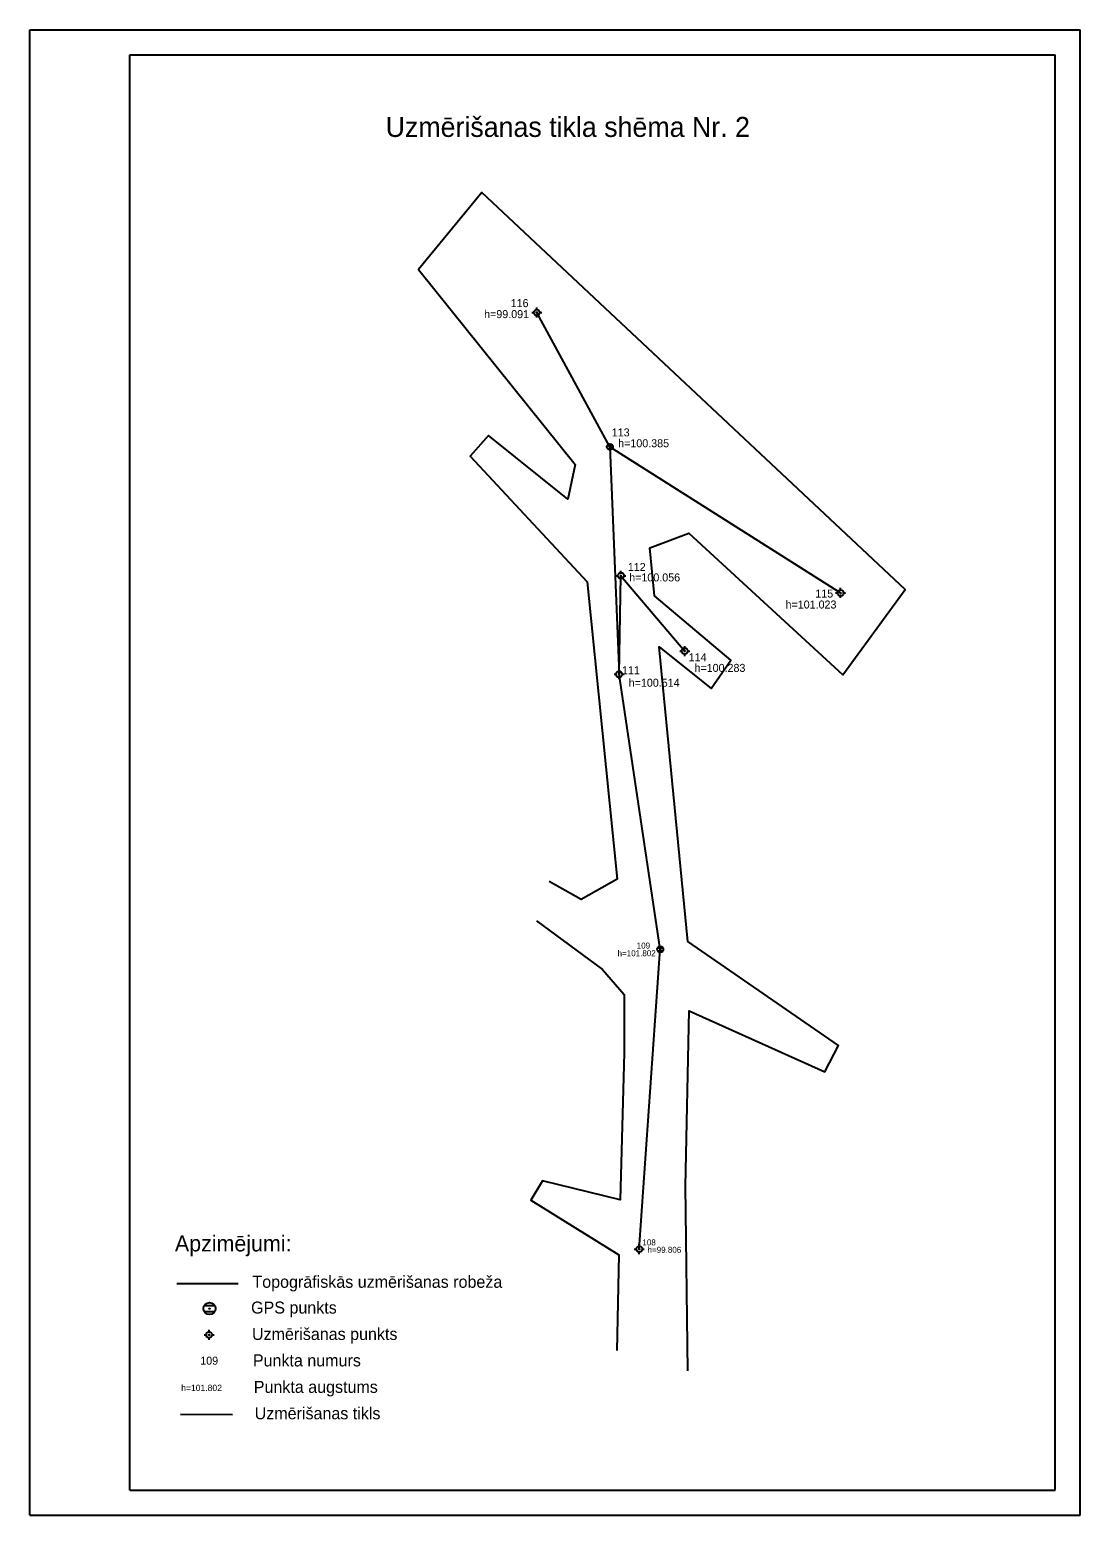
# Model space of a CAD drawing. Extents: x 615321 to 615846, y 263640 to 264383.
import ezdxf

# ---------------------------------------------------------------- set-up
doc = ezdxf.new("R2010")
doc.units = 0
for name, color, linetype in [('Level 19', 7, 'Continuous'), ('Level 25', 7, 'Continuous'), ('Level 63', 7, 'Continuous')]:
    doc.layers.add(name, color=color, linetype=linetype)

msp = doc.modelspace()

# ---------------------------------------------------------------- linework, layer by layer
at = {"layer": 'Level 19'}
for p, q in [((615572.36, 264241.43), (615573.36, 264241.43)), ((615574.86, 264242.93), (615574.86, 264243.93)), ((615611.43, 264174.34), (615574.86, 264241.43)), ((615576.36, 264241.43), (615577.36, 264241.43)), ((615574.86, 264238.93), (615574.86, 264239.93)), ((615610.13, 264175.09), (615612.73, 264175.09)), ((615611.43, 264174.34), (615615.96, 264060.66)), ((615611.43, 264174.34), (615726.66, 264101.3)), ((615610.13, 264173.59), (615612.73, 264173.59)), ((615614.44, 264109.92), (615615.44, 264109.92)), ((615615.96, 264060.66), (615616.94, 264109.92)), ((615616.94, 264111.42), (615616.94, 264112.42)), ((615616.94, 264109.92), (615648.76, 264072.27)), ((615616.94, 264107.42), (615616.94, 264108.42)), ((615618.44, 264109.92), (615619.44, 264109.92)), ((615724.16, 264101.3), (615725.16, 264101.3)), ((615726.66, 264102.8), (615726.66, 264103.8)), ((615728.16, 264101.3), (615729.16, 264101.3)), ((615726.66, 264098.8), (615726.66, 264099.8)), ((615646.26, 264072.27), (615647.26, 264072.27)), ((615648.76, 264073.77), (615648.76, 264074.77)), ((615648.76, 264069.77), (615648.76, 264070.77)), ((615650.26, 264072.27), (615651.26, 264072.27)), ((615615.96, 264062.16), (615615.96, 264063.16)), ((615613.46, 264060.66), (615614.46, 264060.66)), ((615636.56, 263923.23), (615615.96, 264060.66)), ((615615.96, 264058.16), (615615.96, 264059.16)), ((615617.46, 264060.66), (615618.46, 264060.66)), ((615626.06, 263773.35), (615636.56, 263923.23)), ((615635.26, 263923.98), (615637.86, 263923.98)), ((615635.26, 263922.48), (615637.86, 263922.48)), ((615623.56, 263773.35), (615624.56, 263773.35)), ((615626.06, 263774.86), (615626.06, 263775.86)), ((615627.56, 263773.35), (615628.56, 263773.35)), ((615626.06, 263770.86), (615626.06, 263771.86)), ((615408.69, 263745.1), (615413.88, 263745.1)), ((615408.69, 263742.1), (615413.88, 263742.1)), ((615408.61, 263730.53), (615409.61, 263730.53)), ((615411.11, 263732.03), (615411.11, 263733.03)), ((615411.11, 263728.03), (615411.11, 263729.03)), ((615412.61, 263730.53), (615413.61, 263730.53)), ((615422.8, 263690.57), (615396.83, 263690.62))]:
    msp.add_line(p, q, dxfattribs=at)
for centre, radius in [((615574.86, 264241.43), 1.5), ((615574.86, 264241.43), 0.2), ((615611.43, 264174.34), 1.5), ((615611.43, 264174.34), 0.08), ((615616.94, 264109.92), 1.5), ((615616.94, 264109.92), 0.2), ((615726.66, 264101.3), 1.5), ((615726.66, 264101.3), 0.2), ((615648.76, 264072.27), 1.5), ((615648.76, 264072.27), 0.2), ((615615.96, 264060.66), 1.5), ((615615.96, 264060.66), 0.2), ((615636.56, 263923.23), 1.5), ((615636.56, 263923.23), 0.08), ((615626.06, 263773.35), 1.5), ((615626.06, 263773.35), 0.2), ((615411.29, 263743.6), 3), ((615411.29, 263743.6), 0.16), ((615411.11, 263730.53), 1.5), ((615411.11, 263730.53), 0.2)]:
    msp.add_circle(centre, radius, dxfattribs=at)
at = {"layer": 'Level 25'}
msp.add_line((615395.01, 263756.16), (615425.57, 263756.16), dxfattribs=at)
for points in [[(615650.31, 263712.52), (615649.19, 263804.75), (615651.03, 263892.42), (615718.86, 263862), (615725.65, 263875.12), (615650.27, 263927.03), (615636.07, 264074.3), (615661.97, 264053.63), (615671.9, 264067.65), (615633.61, 264099.8), (615631.29, 264123.92), (615650.85, 264131.21), (615727.85, 264060.46), (615758.93, 264103), (615547.44, 264301.47), (615515.7, 264263), (615594.09, 264165.59), (615590.41, 264148.27), (615550.77, 264179.99), (615541.58, 264169.6), (615600.08, 264106.91), (615615.01, 263958.32), (615597.04, 263948.14), (615581.01, 263957.13)], [(615574.69, 263937.47), (615607.77, 263913.06), (615618.57, 263900.65), (615618.57, 263871.49), (615616.58, 263797.94), (615577.64, 263807.5), (615571.84, 263797.84), (615615.86, 263770.49), (615614.87, 263722.66)]]:
    msp.add_lwpolyline(points, dxfattribs=at)
at = {"layer": 'Level 63'}
for p, q in [((615321.46, 263640.32), (615321.46, 264382.82)), ((615321.46, 264382.82), (615846.46, 264382.82)), ((615846.46, 263640.32), (615846.46, 264382.82)), ((615371.46, 263652.82), (615371.46, 264370.32)), ((615371.46, 264370.32), (615833.96, 264370.32)), ((615833.96, 263652.82), (615833.96, 264370.32)), ((615371.46, 263652.82), (615833.96, 263652.82)), ((615321.46, 263640.32), (615846.46, 263640.32))]:
    msp.add_line(p, q, dxfattribs=at)

# ---------------------------------------------------------------- texts
at = {"layer": 'Level 19'}
for s, height, p in [('h=99.091', 4, (615548.54, 264238.68)), (' 116', 4, (615560.33, 264244.16)), (' 113', 4, (615610.85, 264179.56)), ('h=100.385', 4, (615615.53, 264174.13)), ('112', 4, (615620.35, 264112.28)), ('h=100.056', 4, (615621.05, 264107.08)), (' 115', 4, (615712.56, 264099.01)), ('h=101.023', 4, (615699.17, 264093.53)), (' 114', 4, (615649.27, 264067.16)), (' 111', 4, (615615.96, 264060.66)), ('h=100.283', 4, (615653.67, 264061.86)), ('h=100.514', 4, (615620.8, 264054.44)), ('h=101.802', 3, (615615.23, 263919.76)), (' 109', 3, (615623.67, 263923.57)), (' 108', 3, (615626.52, 263775.21)), ('h=99.806', 3, (615630.21, 263771.51)), ('109', 4, (615406.69, 263715.59)), (' h=101.802', 3.2, (615395.98, 263702.4))]:
    msp.add_text(s, height=height, dxfattribs=at).set_placement(p)
at = {"layer": 'Level 63'}
for s, height, p in [('Uzmērišanas tikla shēma Nr. 2', 10, (615499.32, 264329.24)), ('Apzimējumi:', 8, (615394.02, 263772.21)), ('Topogrāfiskās uzmērišanas robeža', 6, (615432.75, 263754.02)), ('GPS punkts', 6, (615432.08, 263741.15)), ('Uzmērišanas punkts', 6, (615432.53, 263727.94)), ('Punkta numurs', 6, (615432.98, 263714.73)), ('Punkta augstums', 6, (615433.42, 263701.51)), ('Uzmērišanas tikls', 6, (615433.87, 263688.3))]:
    msp.add_text(s, height=height, dxfattribs=at).set_placement(p)

doc.saveas('drawing.dxf')
